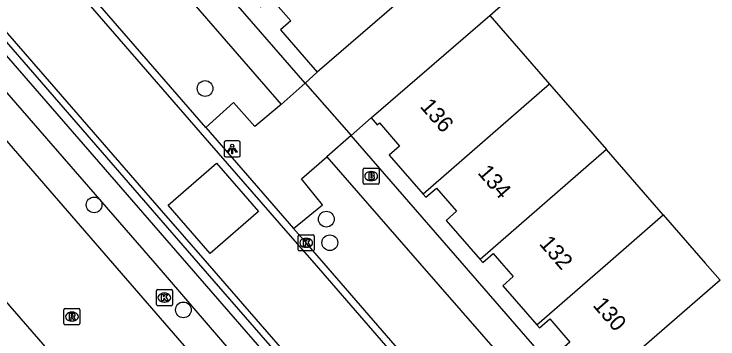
# Model space of a CAD drawing. Extents: x 155888 to 156864, y 383882 to 384671.
# Drawn here: x 156338.76 to 156382.63, y 384245.27 to 384265.52 of the extents above; entities that cross this region are included whole.
import ezdxf

# ---------------------------------------------------------------- set-up
doc = ezdxf.new("R2010")
doc.units = 0
for name, color, linetype in [('IMGEO_Berm_groen', 7, 'Continuous'), ('IMGEO_Boom', 7, 'Continuous'), ('IMGEO_Brandkraan', 7, 'Continuous'), ('IMGEO_Kolk', 7, 'Continuous'), ('IMGEO_Lichtpunt', 7, 'Continuous'), ('IMGEO_Muur', 7, 'Continuous'), ('IMGEO_OVBaan_gesloten', 7, 'Continuous'), ('IMGEO_Pand', 7, 'Continuous'), ('IMGEO_Pand_nummerreeks', 7, 'Continuous'), ('IMGEO_Rijbaan_lokaal_gesloten', 7, 'Continuous'), ('IMGEO_Rijbaan_lokaal_open', 7, 'Continuous'), ('IMGEO_Rioolput', 7, 'Continuous'), ('IMGEO_Voetpad_open', 7, 'Continuous')]:
    doc.layers.add(name, color=color, linetype=linetype)

msp = doc.modelspace()

# ---------------------------------------------------------------- linework, layer by layer
at = {"layer": 'IMGEO_Berm_groen'}
msp.add_lwpolyline([(156364.691, 384230.078), (156347.548, 384250), (156269.795, 384339.498), (156265.985, 384345.065), (156270.967, 384340.448), (156349.508, 384250), (156365.892, 384231.132)], dxfattribs=at)
at = {"layer": 'IMGEO_Boom'}
for centre in [(156350.665, 384260.884), (156343.752, 384253.632), (156358.224, 384252.74), (156358.442, 384251.273), (156349.314, 384247.087)]:
    msp.add_circle(centre, 0.489, dxfattribs=at)
at = {"layer": 'IMGEO_Brandkraan'}
for p, q in [((156360.518, 384254.995), (156360.518, 384255.847)), ((156360.593, 384255.921), (156361.445, 384255.921)), ((156361.519, 384255.847), (156361.519, 384254.995)), ((156361.006, 384255.701), (156361.031, 384255.701)), ((156361.029, 384255.141), (156361.004, 384255.141)), ((156361.445, 384254.921), (156360.593, 384254.921))]:
    msp.add_line(p, q, dxfattribs=at)
for points in [[(156360.518, 384254.995), (156360.518, 384255.847)], [(156360.593, 384255.921), (156361.445, 384255.921)], [(156361.519, 384255.847), (156361.519, 384254.995)], [(156360.866, 384255.621), (156360.866, 384255.221), (156361.079, 384255.221)], [(156361.097, 384255.621), (156360.866, 384255.621)], [(156361.045, 384255.54), (156360.991, 384255.54), (156360.991, 384255.464)], [(156360.991, 384255.464), (156361.044, 384255.464)], [(156361.053, 384255.388), (156360.991, 384255.388), (156360.991, 384255.307)], [(156360.991, 384255.307), (156361.053, 384255.307)], [(156361.445, 384254.921), (156360.593, 384254.921)]]:
    msp.add_lwpolyline(points, dxfattribs=at)
for centre, radius, start, end in [((156360.595, 384255.845), 0.0765, 91.552, 178.448), ((156360.595, 384255.845), 0.0765, 91.552, 178.448), ((156361.443, 384255.845), 0.0765, 1.552, 88.448), ((156361.443, 384255.845), 0.0765, 1.552, 88.448), ((156361.046, 384255.502), 0.0379, 267.8285, 90.9355), ((156361.101, 384255.476), 0.145, 59.4692, 91.5367), ((156361.126, 384255.523), 0.0922, 285.5137, 58.1501), ((156361.131, 384255.331), 0.105, 301.3115, 78.989), ((156360.595, 384254.997), 0.0765, 181.552, 268.448), ((156360.595, 384254.997), 0.0765, 181.552, 268.448), ((156361.054, 384255.347), 0.0404, 269.8759, 90.5077), ((156361.085, 384255.472), 0.251, 268.6676, 293.5347), ((156361.443, 384254.997), 0.0765, 271.552, 358.448), ((156361.443, 384254.997), 0.0765, 271.552, 358.448)]:
    msp.add_arc(centre, radius, start, end, dxfattribs=at)
for centre, major_axis, ratio, start_param, end_param in [((156361.005, 384255.421), (-0.387, 0.002), 0.722429, 4.712389, 7.853982), ((156361.03, 384255.421), (-0.39, 0.002), 0.717154, 1.570796, 4.712389)]:
    msp.add_ellipse(centre, major_axis=major_axis, ratio=ratio, start_param=start_param, end_param=end_param, dxfattribs=at)
at = {"layer": 'IMGEO_Kolk'}
for p, q in [((156356.47, 384250.838), (156356.47, 384251.69)), ((156356.545, 384251.764), (156357.397, 384251.764)), ((156356.958, 384251.544), (156356.983, 384251.544)), ((156357.471, 384251.69), (156357.471, 384250.838)), ((156357.397, 384250.764), (156356.545, 384250.764)), ((156356.981, 384250.984), (156356.956, 384250.984)), ((156347.629, 384247.421), (156347.629, 384248.273)), ((156347.704, 384248.347), (156348.556, 384248.347)), ((156348.117, 384248.127), (156348.142, 384248.127)), ((156348.63, 384248.273), (156348.63, 384247.421)), ((156348.14, 384247.567), (156348.115, 384247.567)), ((156348.556, 384247.347), (156347.704, 384247.347))]:
    msp.add_line(p, q, dxfattribs=at)
for points in [[(156356.47, 384250.838), (156356.47, 384251.69)], [(156356.545, 384251.764), (156357.397, 384251.764)], [(156356.791, 384251.464), (156356.914, 384251.464), (156356.914, 384251.313), (156357.044, 384251.464), (156357.208, 384251.464), (156357.062, 384251.313), (156357.215, 384251.064), (156357.063, 384251.064), (156356.978, 384251.228), (156356.914, 384251.161), (156356.914, 384251.064), (156356.791, 384251.064), (156356.791, 384251.464)], [(156357.471, 384251.69), (156357.471, 384250.838)], [(156357.397, 384250.764), (156356.545, 384250.764)], [(156347.629, 384247.421), (156347.629, 384248.273)], [(156347.704, 384248.347), (156348.556, 384248.347)], [(156347.95, 384248.047), (156348.073, 384248.047), (156348.073, 384247.896), (156348.203, 384248.047), (156348.367, 384248.047), (156348.221, 384247.896), (156348.374, 384247.647), (156348.222, 384247.647), (156348.137, 384247.811), (156348.073, 384247.744), (156348.073, 384247.647), (156347.95, 384247.647), (156347.95, 384248.047)], [(156348.63, 384248.273), (156348.63, 384247.421)], [(156348.556, 384247.347), (156347.704, 384247.347)]]:
    msp.add_lwpolyline(points, dxfattribs=at)
for centre, start, end in [((156356.547, 384251.688), 91.552, 178.448), ((156356.547, 384251.688), 91.552, 178.448), ((156357.395, 384251.688), 1.552, 88.448), ((156357.395, 384251.688), 1.552, 88.448), ((156356.547, 384250.84), 181.552, 268.448), ((156356.547, 384250.84), 181.552, 268.448), ((156357.395, 384250.84), 271.552, 358.448), ((156357.395, 384250.84), 271.552, 358.448), ((156347.706, 384248.271), 91.552, 178.448), ((156347.706, 384248.271), 91.552, 178.448), ((156348.554, 384248.271), 1.552, 88.448), ((156348.554, 384248.271), 1.552, 88.448), ((156347.706, 384247.423), 181.552, 268.448), ((156347.706, 384247.423), 181.552, 268.448), ((156348.554, 384247.423), 271.552, 358.448), ((156348.554, 384247.423), 271.552, 358.448)]:
    msp.add_arc(centre, 0.0765, start, end, dxfattribs=at)
for centre, major_axis, ratio, start_param, end_param in [((156356.957, 384251.264), (-0.387, 0.002), 0.722429, 4.712389, 7.853982), ((156356.982, 384251.264), (-0.39, 0.002), 0.717154, 1.570796, 4.712389), ((156348.116, 384247.847), (-0.387, 0.002), 0.722429, 4.712389, 7.853982), ((156348.141, 384247.847), (-0.39, 0.002), 0.717154, 1.570796, 4.712389)]:
    msp.add_ellipse(centre, major_axis=major_axis, ratio=ratio, start_param=start_param, end_param=end_param, dxfattribs=at)
at = {"layer": 'IMGEO_Lichtpunt'}
for p, q in [((156352.759, 384257.618), (156351.951, 384257.618)), ((156352.759, 384257.618), (156351.951, 384257.618)), ((156351.857, 384257.523), (156351.857, 384256.716)), ((156351.857, 384257.523), (156351.857, 384256.716)), ((156352.853, 384256.716), (156352.853, 384257.523)), ((156352.853, 384256.716), (156352.853, 384257.523)), ((156351.951, 384256.622), (156352.759, 384256.622)), ((156351.951, 384256.622), (156352.759, 384256.622))]:
    msp.add_line(p, q, dxfattribs=at)
for points in [[(156352.231, 384257.187), (156352.27, 384257.159), (156352.082, 384256.897), (156352.044, 384256.924), (156352.231, 384257.187)], [(156352.443, 384257.159), (156352.481, 384257.186), (156352.668, 384256.924), (156352.629, 384256.896), (156352.443, 384257.159)], [(156352.333, 384257.139), (156352.38, 384257.139), (156352.38, 384256.817), (156352.333, 384256.817), (156352.333, 384257.139)]]:
    msp.add_lwpolyline(points, dxfattribs=at)
msp.add_circle((156352.356, 384257.321), 0.0994, dxfattribs=at)
for centre, start, end in [((156351.951, 384257.523), 90, 180), ((156351.951, 384257.523), 90, 180), ((156352.759, 384257.523), 0, 90), ((156352.759, 384257.523), 0, 90), ((156351.951, 384256.716), 180, 270), ((156351.951, 384256.716), 180, 270), ((156352.759, 384256.716), 270, 0), ((156352.759, 384256.716), 270, 360)]:
    msp.add_arc(centre, 0.0946, start, end, dxfattribs=at)
at = {"layer": 'IMGEO_Muur'}
msp.add_lwpolyline([(156368.418, 384265.437), (156380.088, 384275.63)], dxfattribs=at)
at = {"layer": 'IMGEO_OVBaan_gesloten'}
for points in [[(156363.627, 384228.639), (156361.513, 384231.125), (156360.68, 384232.052), (156360.575, 384231.973), (156353.442, 384240.167), (156344.918, 384250), (156310.449, 384289.788), (156259.398, 384348.45)], [(156254.404, 384344.112), (156299.846, 384291.826), (156336.14, 384250), (156374.404, 384205.959), (156378.343, 384201.4)]]:
    msp.add_lwpolyline(points, dxfattribs=at)
at = {"layer": 'IMGEO_Pand'}
for points in [[(156369.076, 384271.757), (156365.593, 384268.752), (156357.657, 384261.906)], [(156353.953, 384266.165), (156354.117, 384265.976), (156354.767, 384266.539), (156356.018, 384265.109), (156355.368, 384264.545), (156357.657, 384261.906)], [(156361.021, 384259.051), (156368.418, 384265.437)], [(156368.418, 384265.437), (156372.141, 384261.153)], [(156372.141, 384261.153), (156364.26, 384254.301)], [(156372.141, 384261.153), (156375.683, 384257.077)], [(156361.021, 384259.051), (156361.389, 384258.611), (156361.548, 384258.741), (156362.792, 384257.299), (156362.143, 384256.737), (156364.26, 384254.301)], [(156375.683, 384257.077), (156367.802, 384250.225)], [(156379.222, 384253.005), (156375.683, 384257.077)], [(156364.26, 384254.301), (156364.432, 384254.104), (156365.081, 384254.668), (156366.332, 384253.23), (156365.683, 384252.666), (156367.802, 384250.225)], [(156371.341, 384246.154), (156375.766, 384250), (156379.222, 384253.005)], [(156379.222, 384253.005), (156381.834, 384250), (156382.765, 384248.929)], [(156367.802, 384250.225), (156367.969, 384250.033), (156368.619, 384250.596), (156369.135, 384250), (156369.865, 384249.156), (156369.217, 384248.591), (156371.341, 384246.154)], [(156382.765, 384248.929), (156374.882, 384242.077)], [(156371.341, 384246.154), (156371.513, 384245.957), (156372.162, 384246.522), (156373.41, 384245.082), (156372.761, 384244.518), (156374.882, 384242.077)]]:
    msp.add_lwpolyline(points, dxfattribs=at)
at = {"layer": 'IMGEO_Rijbaan_lokaal_gesloten'}
for points in [[(156268.182, 384354.901), (156268.706, 384354.213), (156268.937, 384353.913), (156270.932, 384350.999), (156272.094, 384349.06), (156272.56, 384348.305), (156273.043, 384347.563), (156273.546, 384346.832), (156274.066, 384346.114), (156274.603, 384345.409), (156275.158, 384344.718), (156311.817, 384302.54), (156315.512, 384298.282), (156317.194, 384296.335), (156350.366, 384258.146), (156355.834, 384251.857), (156357.459, 384250), (156390.184, 384212.221), (156390.405, 384211.984), (156390.515, 384211.858)], [(156386.787, 384208.599), (156386.636, 384208.775), (156350.811, 384250), (156347.958, 384253.282), (156313.464, 384293.017), (156272.441, 384340.175), (156271.109, 384341.853), (156269.835, 384343.577), (156268.621, 384345.343), (156264.92, 384350.887), (156264.101, 384351.847)]]:
    msp.add_lwpolyline(points, dxfattribs=at)
at = {"layer": 'IMGEO_Rijbaan_lokaal_open'}
for points in [[(156272.151, 384339.898), (156313.168, 384292.747), (156347.631, 384252.995), (156350.238, 384250), (156366.569, 384231.232)], [(156350.713, 384258.448), (156317.542, 384296.636)], [(156350.713, 384258.448), (156356.18, 384252.16)], [(156351.377, 384256.239), (156353.986, 384253.219), (156350.975, 384250.59), (156348.367, 384253.609), (156351.377, 384256.239)], [(156390.873, 384212.147), (156390.747, 384212.292), (156390.526, 384212.529), (156358.068, 384250), (156356.972, 384251.265), (156356.18, 384252.16)]]:
    msp.add_lwpolyline(points, dxfattribs=at)
at = {"layer": 'IMGEO_Rioolput'}
for p, q in [((156341.867, 384246.237), (156341.867, 384247.089)), ((156341.942, 384247.163), (156342.794, 384247.163)), ((156342.868, 384247.089), (156342.868, 384246.237)), ((156342.355, 384246.943), (156342.38, 384246.943)), ((156342.378, 384246.383), (156342.353, 384246.383)), ((156342.794, 384246.163), (156341.942, 384246.163))]:
    msp.add_line(p, q, dxfattribs=at)
for points in [[(156341.867, 384246.237), (156341.867, 384247.089)], [(156341.942, 384247.163), (156342.794, 384247.163)], [(156342.868, 384247.089), (156342.868, 384246.237)], [(156342.456, 384246.861), (156342.204, 384246.863), (156342.204, 384246.463)], [(156342.204, 384246.463), (156342.328, 384246.463), (156342.328, 384246.625), (156342.339, 384246.625)], [(156342.382, 384246.782), (156342.328, 384246.782), (156342.328, 384246.701)], [(156342.328, 384246.701), (156342.38, 384246.701)], [(156342.386, 384246.596), (156342.457, 384246.463), (156342.597, 384246.463), (156342.532, 384246.589)], [(156342.794, 384246.163), (156341.942, 384246.163)]]:
    msp.add_lwpolyline(points, dxfattribs=at)
for centre, radius, start, end in [((156341.944, 384247.087), 0.0765, 91.552, 178.448), ((156341.944, 384247.087), 0.0765, 91.552, 178.448), ((156342.792, 384247.087), 0.0765, 1.552, 88.448), ((156342.792, 384247.087), 0.0765, 1.552, 88.448), ((156342.338, 384246.572), 0.0533, 26.0293, 88.6989), ((156342.364, 384246.89), 0.19, 274.7715, 282.9687), ((156342.388, 384246.686), 0.0964, 77.0061, 93.1865), ((156342.402, 384246.743), 0.0378, 276.6634, 79.6772), ((156342.455, 384246.751), 0.109, 350.3612, 89.416), ((156342.453, 384246.751), 0.112, 277.5842, 350.9817), ((156342.437, 384246.536), 0.108, 29.5134, 73.7905), ((156341.944, 384246.239), 0.0765, 181.552, 268.448), ((156341.944, 384246.239), 0.0765, 181.552, 268.448), ((156342.792, 384246.239), 0.0765, 271.552, 358.448), ((156342.792, 384246.239), 0.0765, 271.552, 358.448)]:
    msp.add_arc(centre, radius, start, end, dxfattribs=at)
for centre, major_axis, ratio, start_param, end_param in [((156342.354, 384246.663), (-0.387, 0.002), 0.722429, 4.712389, 7.853982), ((156342.379, 384246.663), (-0.39, 0.002), 0.717154, 1.570796, 4.712389)]:
    msp.add_ellipse(centre, major_axis=major_axis, ratio=ratio, start_param=start_param, end_param=end_param, dxfattribs=at)
at = {"layer": 'IMGEO_Voetpad_open'}
for points in [[(156356.906, 384261.209), (156321.082, 384302.387)], [(156319.627, 384301.093), (156355.418, 384259.893)], [(156368.418, 384265.437), (156380.088, 384275.63)], [(156357.657, 384261.906), (156356.906, 384261.209)], [(156356.906, 384261.209), (156355.418, 384259.893)], [(156356.906, 384261.209), (156359.778, 384257.949)], [(156355.418, 384259.893), (156353.775, 384258.517), (156352.432, 384260.017), (156350.713, 384258.448)], [(156359.778, 384257.949), (156361.021, 384259.051)], [(156359.778, 384257.949), (156358.247, 384256.625)], [(156388.463, 384224.919), (156366.682, 384250), (156359.778, 384257.949)], [(156356.18, 384252.16), (156357.979, 384253.64), (156356.685, 384255.261), (156358.247, 384256.625)], [(156358.247, 384256.625), (156364.03, 384250), (156379.347, 384232.453)]]:
    msp.add_lwpolyline(points, dxfattribs=at)

# ---------------------------------------------------------------- texts
at = {"layer": 'IMGEO_Pand_nummerreeks'}
for s, rotation, p in [('136', 310.993, (156364.022, 384259.74)), ('134', 310.993, (156367.611, 384255.611)), ('132', 311.0122, (156371.447, 384251.187)), ('130', 310.993, (156374.79, 384247.349))]:
    msp.add_text(s, height=1, rotation=rotation, dxfattribs=at).set_placement(p)

doc.saveas('drawing.dxf')
